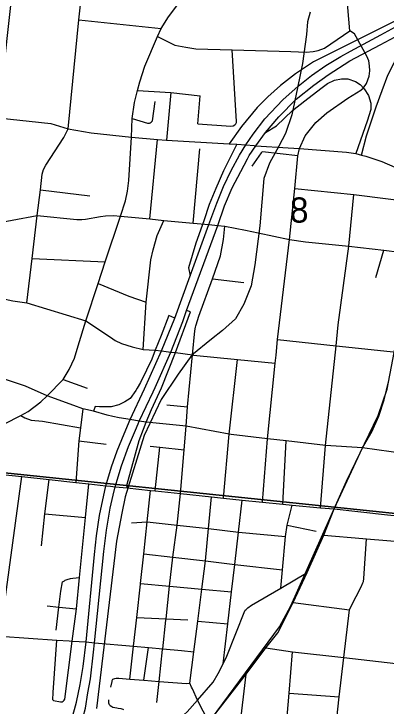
# Model space of a CAD drawing. Extents: x -8.2 to 38.5, y -0.1 to 21.9.
# Drawn here: x 7.75 to 8.37, y 15.475 to 16.627 of the extents above; entities that cross this region are included whole.
import ezdxf

# ---------------------------------------------------------------- set-up
doc = ezdxf.new("R2010")
doc.units = 0
for name, color, linetype in [('GM_X_Adjacent_County_Text', 7, 'Continuous'), ('GM_X_Airport_Location_Class_1', 7, 'Continuous'), ('GM_X_Airport_Location_Class_3', 7, 'Continuous'), ('GM_X_County_Road_Text', 7, 'Continuous'), ('GM_X_Interstate_Location', 7, 'Continuous'), ('GM_X_State_Location', 7, 'Continuous'), ('GM_X_Township_Subdivision_Text', 7, 'Continuous'), ('GM_X_Township_Text', 7, 'Continuous'), ('GM_X_US_Location', 7, 'Continuous')]:
    doc.layers.add(name, color=color, linetype=linetype)

msp = doc.modelspace()

# ---------------------------------------------------------------- linework, layer by layer
at = {"layer": 'GM_X_Adjacent_County_Text'}
for points in [[(7.7722, 16.8835), (8.7794, 16.8117), (8.6736, 15.7659), (7.66, 15.8712)], [(7.66, 15.8712), (8.6736, 15.7659), (8.6117, 15.0774), (8.5928, 15.0619), (8.5723, 15.0415), (8.5525, 15.0184), (8.5405, 15.0046), (8.5226, 14.9831), (8.5094, 14.9667), (8.4937, 14.9454), (8.4864, 14.9373), (8.469, 14.9221), (8.4519, 14.9028), (8.4387, 14.8852), (8.4261, 14.8666), (8.4156, 14.8524), (8.4049, 14.847), (8.3954, 14.8305), (8.3869, 14.8201), (8.3765, 14.8112), (8.3645, 14.8016), (8.3536, 14.7875), (8.3469, 14.777), (7.5202, 14.8634)]]:
    msp.add_lwpolyline(points, close=True, dxfattribs=at)
at = {"layer": 'GM_X_Airport_Location_Class_1'}
for p, q in [((8.2838, 15.8035), (8.3312, 15.9052)), ((8.2666, 15.76), (8.2838, 15.8035)), ((8.2386, 15.6979), (8.2666, 15.76)), ((8.2155, 15.6477), (8.2386, 15.6979)), ((8.1373, 15.5285), (8.1698, 15.5723)), ((8.0753, 15.4486), (8.1373, 15.5285))]:
    msp.add_line(p, q, dxfattribs=at)
for points in [[(8.3312, 15.9052), (8.3463, 15.9315), (8.3581, 15.9575), (8.3671, 15.9851), (8.3745, 16.0148)], [(8.1698, 15.5723), (8.1898, 15.5975), (8.2003, 15.618), (8.2155, 15.6477)]]:
    msp.add_lwpolyline(points, dxfattribs=at)
at = {"layer": 'GM_X_Airport_Location_Class_3'}
for p, q in [((8.2838, 15.8035), (8.3312, 15.9052)), ((8.2666, 15.76), (8.2838, 15.8035)), ((8.2386, 15.6979), (8.2666, 15.76)), ((8.2155, 15.6477), (8.2386, 15.6979)), ((8.1373, 15.5285), (8.1698, 15.5723)), ((8.0753, 15.4486), (8.1373, 15.5285))]:
    msp.add_line(p, q, dxfattribs=at)
for points in [[(7.946, 16.4217), (7.9476, 16.453), (7.9511, 16.4796), (7.9563, 16.4998), (7.9601, 16.514), (7.9683, 16.54), (7.9894, 16.5894), (7.9956, 16.6027), (8.008, 16.6219), (8.0315, 16.6543), (8.0429, 16.6676), (8.057, 16.6884), (8.0871, 16.7285), (8.1303, 16.7819), (8.1686, 16.8536), (8.1932, 16.8971), (8.2099, 16.9299), (8.226, 16.9638), (8.2398, 16.9975), (8.2596, 17.035), (8.2822, 17.0786)], [(7.8059, 15.9913), (7.8322, 16.0187), (7.8426, 16.0355), (7.8511, 16.0544), (7.8575, 16.075), (7.8703, 16.1164), (7.8908, 16.1786), (7.9024, 16.2143), (7.9277, 16.2907), (7.9361, 16.3159), (7.9396, 16.3323), (7.942, 16.3498), (7.946, 16.4217)], [(8.3312, 15.9052), (8.3463, 15.9315), (8.3581, 15.9575), (8.3671, 15.9851), (8.3745, 16.0148)], [(7.6718, 15.8654), (7.6726, 15.8672), (7.6765, 15.8737), (7.6884, 15.8923), (7.7048, 15.9142), (7.717, 15.929), (7.7347, 15.9451), (7.7619, 15.959), (7.7744, 15.9656), (7.7953, 15.9816), (7.8059, 15.9913)], [(8.1698, 15.5723), (8.1898, 15.5975), (8.2003, 15.618), (8.2155, 15.6477)]]:
    msp.add_lwpolyline(points, dxfattribs=at)
at = {"layer": 'GM_X_Interstate_Location'}
for points in [[(8.3294, 16.3922), (8.3379, 16.4241), (8.3539, 16.4722), (8.3638, 16.4997), (8.3732, 16.5252), (8.3839, 16.5457), (8.3974, 16.5664), (8.4098, 16.5817), (8.4244, 16.5959), (8.4419, 16.6106), (8.4659, 16.626), (8.491, 16.6433), (8.5096, 16.6566), (8.5335, 16.6754), (8.5598, 16.6981), (8.5822, 16.722), (8.6051, 16.7481), (8.6296, 16.778), (8.6398, 16.7943)], [(8.5546, 16.7195), (8.5099, 16.6864), (8.5097, 16.6862), (8.5003, 16.6793), (8.4881, 16.6704), (8.4742, 16.6612), (8.4589, 16.6515), (8.4493, 16.646), (8.4259, 16.6347), (8.3971, 16.6211), (8.2495, 16.5475), (8.2195, 16.5276), (8.1943, 16.5081), (8.1731, 16.4888), (8.1558, 16.4714), (8.1295, 16.4399), (8.1088, 16.4109)], [(8.1692, 16.4298), (8.1876, 16.441), (8.2145, 16.4664), (8.235, 16.4822), (8.2616, 16.5029), (8.2729, 16.5111), (8.2846, 16.5168), (8.2959, 16.519), (8.3064, 16.5188), (8.3194, 16.5147), (8.3271, 16.5093), (8.3339, 16.5022), (8.3408, 16.4914), (8.3449, 16.4784), (8.3451, 16.468), (8.3388, 16.4483), (8.3201, 16.3946)], [(8.1219, 16.4101), (8.0996, 16.3659), (8.0866, 16.3368), (8.0757, 16.3097), (8.0668, 16.2828), (8.0535, 16.2458), (8.0414, 16.2044), (8.0442, 16.1911)], [(7.9388, 15.8384), (7.9392, 15.8448), (7.9588, 15.9171), (7.966, 15.9363), (7.9706, 15.9478), (7.9793, 15.9687), (7.9961, 16.0051), (8.0197, 16.0635), (8.0446, 16.1315), (8.0379, 16.1336)], [(8.0186, 16.1207), (8.0085, 16.125), (7.9958, 16.0918), (7.9859, 16.0673), (7.9799, 16.0524), (7.971, 16.0341), (7.9612, 16.0137), (7.9557, 16.0042)], [(7.9557, 16.0042), (7.9534, 16.0003), (7.9439, 15.9874), (7.9352, 15.9816), (7.9249, 15.9765), (7.9125, 15.9733), (7.9016, 15.9733), (7.893, 15.9735), (7.8858, 15.9739), (7.8831, 15.9663)]]:
    msp.add_lwpolyline(points, dxfattribs=at)
at = {"layer": 'GM_X_State_Location'}
for points in [[(8.1396, 16.3859), (8.1424, 16.3912), (8.1532, 16.4078), (8.1692, 16.4298), (8.1916, 16.4559), (8.2208, 16.4854), (8.2499, 16.5087), (8.2738, 16.5259), (8.3097, 16.5487), (8.3607, 16.5756), (8.4269, 16.611), (8.4668, 16.6344)], [(7.8466, 15.4534), (7.8544, 15.4818), (7.8608, 15.5115), (7.8657, 15.5412), (7.8707, 15.582), (7.8845, 15.7273), (7.888, 15.7586), (7.8929, 15.7924), (7.9034, 15.842), (7.9131, 15.8736), (7.9225, 15.9003), (7.9338, 15.9286), (7.9439, 15.9521), (7.9679, 16.0032), (7.996, 16.0662), (8.0186, 16.1207), (8.0442, 16.1911), (8.0752, 16.2764), (8.0885, 16.3124), (8.0997, 16.3401), (8.1123, 16.3665), (8.1261, 16.3919), (8.1366, 16.409), (8.1487, 16.4267), (8.1681, 16.4522), (8.1982, 16.4843), (8.2237, 16.5069), (8.246, 16.5246), (8.2698, 16.541), (8.2947, 16.5563), (8.3111, 16.5652), (8.3618, 16.5923), (8.4165, 16.622)], [(7.9825, 15.9981), (7.9858, 16.0052), (8.012, 16.0644), (8.0317, 16.1151), (8.0379, 16.1336), (8.0903, 16.2747), (8.101, 16.3078), (8.1142, 16.3379), (8.1282, 16.3649), (8.1396, 16.3859)], [(7.9574, 15.9452), (7.9593, 15.9496), (7.9825, 15.9981)], [(7.9159, 15.8262), (7.9193, 15.8402), (7.9297, 15.8753), (7.9415, 15.9073), (7.9529, 15.9345), (7.9574, 15.9452)], [(7.8827, 15.5653), (7.8845, 15.5808), (7.9003, 15.7328), (7.9045, 15.7683), (7.9106, 15.8047), (7.9159, 15.8262)], [(7.8466, 15.3944), (7.8617, 15.4432), (7.8694, 15.4718), (7.8736, 15.4972), (7.8777, 15.5207), (7.8827, 15.5653)]]:
    msp.add_lwpolyline(points, dxfattribs=at)
at = {"layer": 'GM_X_Township_Subdivision_Text'}
for p, q in [((7.8588, 16.6169), (7.9956, 16.6027)), ((8.0116, 16.4961), (8.0048, 16.4171)), ((8.0567, 16.444), (8.0607, 16.4906)), ((7.9769, 16.2862), (7.9894, 16.418)), ((8.0489, 16.2786), (8.0602, 16.4023)), ((7.7947, 16.3341), (7.8767, 16.3244)), ((8.3533, 16.1887), (8.3664, 16.234)), ((7.7808, 16.2198), (7.9024, 16.2143)), ((8.0814, 16.1861), (8.1335, 16.1804)), ((7.8322, 16.0187), (7.8726, 16.0046)), ((8.0053, 15.9764), (8.0398, 15.973)), ((7.8587, 15.9167), (7.9043, 15.911)), ((8.1985, 15.8113), (8.2041, 15.9167)), ((7.9854, 15.8336), (7.9935, 15.9059)), ((7.8019, 15.7955), (7.8696, 15.7894)), ((8.2055, 15.7765), (8.2539, 15.7663)), ((8.2155, 15.6477), (8.3094, 15.6355)), ((8.0567, 15.6169), (8.1067, 15.612)), ((7.9667, 15.5184), (7.9745, 15.5726)), ((8.2088, 15.4969), (8.2924, 15.4906))]:
    msp.add_line(p, q, dxfattribs=at)
for points in [[(8.3098, 16.5988), (8.3043, 16.6644), (8.2974, 16.6978), (8.296, 16.707), (8.2963, 16.7191), (8.2996, 16.7495)], [(7.9894, 16.5894), (8.0184, 16.5748), (8.0365, 16.5717), (8.0535, 16.5691), (8.1139, 16.5673), (8.2118, 16.5644), (8.2372, 16.5636), (8.249, 16.5645), (8.2573, 16.5659), (8.2677, 16.5698), (8.3098, 16.5988)], [(8.2259, 16.4031), (8.2357, 16.4244), (8.2533, 16.4465), (8.2717, 16.4627), (8.3064, 16.4867), (8.3284, 16.5002), (8.3328, 16.5039), (8.3378, 16.5111), (8.3419, 16.5234), (8.3435, 16.5323), (8.3429, 16.5409), (8.3415, 16.5491), (8.338, 16.5569), (8.3176, 16.5937), (8.3098, 16.5988)], [(8.0567, 16.444), (8.1118, 16.4401), (8.1155, 16.4408), (8.1182, 16.4422), (8.1202, 16.4443), (8.121, 16.4466), (8.121, 16.4478), (8.1139, 16.5673)], [(7.9563, 16.4998), (8.0116, 16.4961), (8.0607, 16.4906)], [(7.9476, 16.453), (7.9731, 16.4454), (7.9763, 16.4453), (7.9775, 16.4457), (7.979, 16.4467), (7.9805, 16.4484), (7.981, 16.4494), (7.9857, 16.4812)], [(8.1645, 15.8144), (8.1729, 15.9203), (8.1856, 16.0457), (8.187, 16.0594), (8.1896, 16.0853), (8.2092, 16.2518), (8.2184, 16.3366), (8.2232, 16.3911), (8.2259, 16.4031)], [(8.2232, 16.3911), (8.1647, 16.3975), (8.1633, 16.397), (8.162, 16.3959), (8.1469, 16.3738)], [(8.2184, 16.3366), (8.3165, 16.3267), (8.4355, 16.3118)], [(8.261, 15.8053), (8.2696, 15.9089), (8.2871, 16.0748), (8.2907, 16.1095), (8.3083, 16.2406), (8.3165, 16.3267)], [(7.7722, 16.1461), (7.7808, 16.2198), (7.7894, 16.2915)], [(7.9656, 16.0684), (7.9708, 16.1472), (7.9786, 16.2181), (7.9823, 16.2344), (7.989, 16.2584), (8.0003, 16.2834)], [(8.0541, 16.1099), (8.0585, 16.1239), (8.0814, 16.1861), (8.0944, 16.2246), (8.0994, 16.2515), (8.1019, 16.2736)], [(7.4477, 16.1873), (7.4888, 16.1812), (7.5301, 16.1771), (7.6131, 16.1669), (7.6931, 16.161), (7.7251, 16.1549), (7.7488, 16.1499), (7.7722, 16.1461), (7.8703, 16.1164), (7.9115, 16.0891), (7.9191, 16.0839), (7.9294, 16.0789), (7.9474, 16.073), (7.9656, 16.0684), (7.9859, 16.0673), (7.996, 16.0662), (8.012, 16.0644), (8.0197, 16.0635), (8.048, 16.0596), (8.0494, 16.0595), (8.1227, 16.0521), (8.1856, 16.0457)], [(7.8908, 16.1786), (7.9418, 16.1574), (7.9708, 16.1472)], [(7.9886, 15.4814), (7.9923, 15.5164), (7.9981, 15.5695), (7.9982, 15.5704), (8.0036, 15.6184), (8.0038, 15.6206), (8.0098, 15.6747), (8.0152, 15.7231), (8.0224, 15.7764), (8.0277, 15.8293), (8.0338, 15.9017), (8.0373, 15.9411), (8.0398, 15.973), (8.048, 16.0596), (8.0519, 16.0997), (8.0531, 16.106), (8.0536, 16.108), (8.0541, 16.1099)], [(8.1896, 16.0853), (8.2871, 16.0748), (8.3875, 16.064)], [(8.0997, 15.8211), (8.1092, 15.9278), (8.1227, 16.0521)], [(7.7619, 15.959), (7.7685, 15.955), (7.7792, 15.9513), (7.7981, 15.9492), (7.8614, 15.9385)], [(7.9771, 15.9076), (7.9935, 15.9059), (8.0338, 15.9017)], [(7.7197, 15.5285), (7.7269, 15.5916), (7.7638, 15.8573)], [(7.7963, 15.742), (7.8019, 15.7955), (7.809, 15.8524)], [(7.8151, 15.4856), (7.8163, 15.4849), (7.8281, 15.4824), (7.8309, 15.4827), (7.8327, 15.4834), (7.8343, 15.4851), (7.8352, 15.4868), (7.8476, 15.5836), (7.8545, 15.6374), (7.8597, 15.6893), (7.8696, 15.7894), (7.8751, 15.8451)], [(7.9434, 15.5202), (7.9496, 15.5749), (7.9551, 15.6229), (7.9614, 15.6784), (7.9614, 15.6791), (7.9666, 15.7288), (7.9721, 15.7818), (7.978, 15.8343)], [(8.0476, 15.5041), (8.0463, 15.5069), (8.0434, 15.5134), (8.0501, 15.5657), (8.0567, 15.6169), (8.0634, 15.6699), (8.0695, 15.7168), (8.0745, 15.771), (8.0795, 15.8233)], [(8.0989, 15.5457), (8.1067, 15.612), (8.113, 15.6655), (8.1184, 15.7111), (8.1247, 15.7649), (8.1308, 15.818)], [(8.195, 15.6716), (8.1977, 15.7019), (8.2025, 15.7574), (8.2055, 15.7765), (8.2136, 15.8096)], [(7.9462, 15.78), (7.9721, 15.7818), (8.0224, 15.7764), (8.0745, 15.771), (8.1247, 15.7649), (8.2025, 15.7574)], [(8.2666, 15.76), (8.3315, 15.754), (8.3377, 15.7535), (8.4122, 15.7477)], [(8.2849, 15.4235), (8.2924, 15.4906), (8.2997, 15.5561), (8.3094, 15.6355), (8.3122, 15.6418), (8.3287, 15.6738), (8.3318, 15.6806), (8.3324, 15.6828), (8.3331, 15.6874), (8.3377, 15.7535)], [(7.9666, 15.7288), (8.0152, 15.7231), (8.0695, 15.7168), (8.1184, 15.7111), (8.1977, 15.7019)], [(7.8314, 15.6819), (7.8346, 15.6838), (7.836, 15.6846), (7.8392, 15.6861), (7.8447, 15.6878), (7.8484, 15.6883), (7.8597, 15.6893)], [(7.8209, 15.6016), (7.8254, 15.6402), (7.8285, 15.6667), (7.8314, 15.6819)], [(7.9614, 15.6791), (8.0098, 15.6747), (8.0634, 15.6699), (8.113, 15.6655)], [(7.8057, 15.6421), (7.8254, 15.6402), (7.8545, 15.6374)], [(7.3059, 15.6307), (7.3939, 15.6223), (7.5239, 15.61), (7.5768, 15.6049), (7.6323, 15.5997), (7.6932, 15.5939), (7.7269, 15.5916), (7.8218, 15.5853), (7.8423, 15.584), (7.8476, 15.5836), (7.8707, 15.582), (7.8845, 15.5808), (7.9496, 15.5749), (7.9745, 15.5726), (7.9982, 15.5704), (8.0296, 15.5676), (8.0501, 15.5657)], [(7.9551, 15.6229), (8.0038, 15.6206), (8.0399, 15.619)], [(7.8151, 15.4856), (7.8156, 15.4978), (7.8218, 15.5853)], [(8.0785, 15.0299), (8.1037, 15.059), (8.1152, 15.0743), (8.1222, 15.0863), (8.1287, 15.1018), (8.1478, 15.1519), (8.1618, 15.1927), (8.1747, 15.2402), (8.1872, 15.3239), (8.2035, 15.4317), (8.2088, 15.4969), (8.2144, 15.5657)], [(8.1698, 15.5723), (8.2144, 15.5657), (8.2997, 15.5561), (8.3867, 15.5464)], [(8.1065, 15.2855), (8.1092, 15.2876), (8.1107, 15.289), (8.1114, 15.2898), (8.112, 15.2911), (8.1269, 15.4394), (8.1373, 15.5285)], [(7.9117, 15.5071), (7.9138, 15.5161), (7.9143, 15.5181), (7.9154, 15.5199), (7.9166, 15.5208), (7.9184, 15.5214), (7.9207, 15.5216), (7.9219, 15.5217), (7.9253, 15.5216), (7.9434, 15.5202), (7.9667, 15.5184), (7.9923, 15.5164), (8.0381, 15.5128), (8.0434, 15.5134)], [(8.0753, 15.4486), (8.056, 15.4851), (8.0476, 15.5041)], [(7.9082, 15.4858), (7.9081, 15.4805), (7.9083, 15.479), (7.909, 15.4779), (7.9107, 15.4763), (7.9137, 15.4744), (7.9152, 15.4737), (7.922, 15.4724), (7.9242, 15.4719), (7.9287, 15.4711), (7.932, 15.4704), (7.9327, 15.4699)]]:
    msp.add_lwpolyline(points, dxfattribs=at)
at = {"layer": 'GM_X_Township_Text'}
msp.add_line((7.8504, 15.9754), (7.8059, 15.9913), dxfattribs=at)
for points in [[(7.8406, 16.436), (7.8588, 16.6169), (7.8647, 16.6731), (7.8697, 16.7152), (7.8738, 16.7545), (7.8792, 16.8072), (7.8823, 16.8352), (7.8894, 16.9064), (7.897, 16.9598), (7.9021, 17.007), (7.9062, 17.0565), (7.9126, 17.1222), (7.9234, 17.1997), (7.9423, 17.2883), (7.9446, 17.2981), (7.9476, 17.306), (7.9515, 17.3133), (7.9594, 17.3244), (7.9859, 17.3537), (7.995, 17.3655), (8.0023, 17.3799)], [(7.48, 16.4794), (7.5213, 16.4747), (7.5693, 16.4697), (7.6456, 16.4623), (7.7234, 16.4541), (7.8117, 16.4446), (7.8406, 16.436), (7.8792, 16.429), (7.946, 16.4217)], [(7.7894, 16.2915), (7.7947, 16.3341), (7.7975, 16.3605), (7.7995, 16.3681), (7.8036, 16.3755), (7.8337, 16.4214), (7.8406, 16.436)], [(7.946, 16.4217), (7.9894, 16.418), (8.0048, 16.4171), (8.1088, 16.4109), (8.1219, 16.4101), (8.1366, 16.409), (8.1503, 16.408)], [(8.1503, 16.408), (8.1532, 16.4078), (8.207, 16.4043)], [(8.207, 16.4043), (8.2259, 16.4031), (8.3041, 16.3971), (8.3201, 16.3946), (8.3294, 16.3922), (8.3367, 16.3903), (8.3631, 16.3814), (8.4486, 16.3441)], [(7.1853, 16.3144), (7.2361, 16.3091), (7.243, 16.3083), (7.2818, 16.3046), (7.3165, 16.3013), (7.3275, 16.3004), (7.3716, 16.2953), (7.4583, 16.2867), (7.5041, 16.2819), (7.5475, 16.2771), (7.6249, 16.2702), (7.6599, 16.2664), (7.6685, 16.2667), (7.6775, 16.2685), (7.7053, 16.2759), (7.7894, 16.2915), (7.8552, 16.2848), (7.8636, 16.2848), (7.8697, 16.2853), (7.8945, 16.2901), (7.9029, 16.2911), (7.9164, 16.2916), (7.9277, 16.2907)], [(7.9277, 16.2907), (7.9769, 16.2862), (8.0003, 16.2834), (8.0489, 16.2786), (8.0752, 16.2764), (8.0903, 16.2747), (8.1019, 16.2736), (8.1359, 16.2671), (8.1571, 16.2625), (8.1832, 16.257), (8.2092, 16.2518), (8.2358, 16.2478), (8.3083, 16.2406), (8.3664, 16.234), (8.4186, 16.2274)], [(7.8059, 15.9913), (7.7697, 16.0076), (7.7175, 16.0247)], [(7.9153, 15.9574), (7.9057, 15.9596), (7.8831, 15.9663), (7.8652, 15.9702), (7.8504, 15.9754)], [(7.8652, 15.9702), (7.8614, 15.9385), (7.8587, 15.9167), (7.8533, 15.8476)], [(7.9593, 15.9496), (7.9439, 15.9521), (7.9259, 15.955), (7.9153, 15.9574)], [(7.9817, 15.9467), (7.9706, 15.9478), (7.9593, 15.9496)], [(8.3312, 15.9052), (8.2696, 15.9089), (8.2041, 15.9167), (8.1729, 15.9203), (8.1123, 15.9275), (8.1092, 15.9278), (8.0373, 15.9411), (7.9817, 15.9467)], [(8.9128, 15.8742), (8.873, 15.866), (8.8684, 15.8665), (8.7664, 15.8788), (8.7158, 15.8849), (8.7125, 15.8851), (8.7094, 15.8847), (8.702, 15.8825), (8.6849, 15.8746), (8.6778, 15.8715), (8.67, 15.8698), (8.6616, 15.8693), (8.652, 15.87), (8.608, 15.8746), (8.5146, 15.8851), (8.4265, 15.8917), (8.3312, 15.9052)], [(7.6736, 15.867), (7.7147, 15.8624), (7.7638, 15.8573), (7.809, 15.8524), (7.8533, 15.8476), (7.8751, 15.8451), (7.9034, 15.842), (7.9113, 15.8411)], [(7.9113, 15.8411), (7.9193, 15.8402), (7.9388, 15.8384), (7.978, 15.8343), (7.9854, 15.8336), (8.0277, 15.8293), (8.0795, 15.8233), (8.0997, 15.8211), (8.1308, 15.818), (8.1645, 15.8144), (8.1985, 15.8113), (8.2136, 15.8096), (8.261, 15.8053), (8.2838, 15.8035)], [(8.2838, 15.8035), (8.3728, 15.7938), (8.4162, 15.7891), (8.5051, 15.779), (8.5645, 15.7726), (8.5957, 15.7695)], [(7.8426, 15.3429), (7.8454, 15.3471), (7.8495, 15.353), (7.8564, 15.3593), (7.8653, 15.3652), (7.9318, 15.4044), (7.9917, 15.4396), (8.0223, 15.4527), (8.0291, 15.4568), (8.0388, 15.4657), (8.056, 15.4851), (8.0825, 15.515), (8.0907, 15.5293), (8.0989, 15.5457), (8.1052, 15.5582), (8.135, 15.6336), (8.1357, 15.6349), (8.137, 15.6363), (8.14, 15.6388), (8.1462, 15.6433), (8.195, 15.6716), (8.2386, 15.6979)]]:
    msp.add_lwpolyline(points, dxfattribs=at)
at = {"layer": 'GM_X_US_Location'}
for points in [[(7.7503, 14.9442), (7.8185, 15.1058), (7.9026, 15.2232), (8.0796, 15.4541), (8.1926, 15.6071), (8.2114, 15.6422), (8.3044, 15.8494), (8.3571, 15.959), (8.372, 16.0026), (8.4313, 16.3134), (8.4591, 16.3689), (8.4728, 16.3801), (8.5314, 16.4108), (8.5554, 16.4293), (8.6274, 16.4985), (8.663, 16.5204), (8.6911, 16.5612), (8.7059, 16.5889), (8.7276, 16.609), (8.76, 16.6219), (8.7858, 16.6195), (8.8049, 16.6167), (8.9389, 16.5395), (8.9634, 16.5287)], [(8.2441, 16.6299), (8.2392, 16.6137), (8.2376, 16.5926), (8.2309, 16.5443), (8.2226, 16.5038), (8.2133, 16.459), (8.2028, 16.4282), (8.1914, 16.4072), (8.1761, 16.3788), (8.1664, 16.3529), (8.1599, 16.2744), (8.1518, 16.2096), (8.1453, 16.1748), (8.1332, 16.144), (8.1194, 16.1197), (8.0978, 16.1005), (8.0796, 16.0857), (8.0466, 16.059), (8.0239, 16.0274), (7.9958, 15.9856), (7.9675, 15.9256), (7.9357, 15.8233), (7.93, 15.7966), (7.9211, 15.7497), (7.8879, 15.4711)]]:
    msp.add_lwpolyline(points, dxfattribs=at)

# ---------------------------------------------------------------- texts
at = {"layer": 'GM_X_County_Road_Text'}
msp.add_text('8', height=0.0419, rotation=0, dxfattribs=at).set_placement((8.21, 16.2798))

doc.saveas('drawing.dxf')
